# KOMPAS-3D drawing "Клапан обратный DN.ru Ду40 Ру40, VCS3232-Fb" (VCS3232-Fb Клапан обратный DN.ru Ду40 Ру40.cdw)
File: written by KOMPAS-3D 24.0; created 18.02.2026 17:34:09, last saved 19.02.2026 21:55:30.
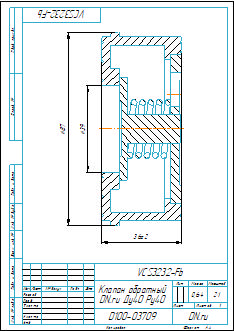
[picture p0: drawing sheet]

Document properties: v313: 1; D: 58; d: 20; a: 1; L: 28; Артикул: D100-03709; Автор: R2D2; Форматы листов документа: A4; Полное имя файла: VCS3232-Fb Клапан обратный DN.ru Ду40 Ру40.m3d; Масса: 0.64; Наименование: Клапан обратный DN.ru Ду40 Ру40; Количество листов документа: 1; Примечание: D100-03709

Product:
- Body: Тело 1  | qty 1
    Масса: 0.487013
- Body: Тело 2  | qty 1
    Масса: 0.16409
- Part/product: Клапан обратный DN.ru Ду40 Ру40  | designation VCS3232-Fb
    Масса: 0.64
    Примечание: D100-03709
    additional columns: 1; D100-03709

Views: Вид 1, Местный разрез 1, Справа
Referenced files in E:\Работа\Зайцев\VCS3232-Fb Клапан обратный DN.ru Ду15-100\DN32\: VCS3232-Fb Клапан обратный DN.ru Ду32 Ру40.m3d
Referenced files in E:\Работа\Зайцев\VCS3232-Fb Клапан обратный DN.ru Ду15-100\DN25\: VCS3232-Fb Клапан обратный DN.ru Ду25 Ру40.m3d
Referenced files in E:\Работа\Зайцев\VCS3232-Fb Клапан обратный DN.ru Ду15-100\DN40\: VCS3232-Fb Клапан обратный DN.ru Ду40 Ру40.m3d
Referenced files in E:\Работа\Зайцев\Для компаса\: чертеж DN.ru.cdt
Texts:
  VCS3232-Fb
  чертеж DN.ru.cdt
  Клапан обратный
  DN.ru Ду40 Ру40
  prop
  Клапан обратный DN.ru Ду40 Ру40
  VCS3232-Fb Клапан обратный DN.ru Ду40 Ру40
Dimensions and other numbers on the sheet: 0; 3; 2; 4; 36±2; 87; 39; 6; 2:1; 1; 0,64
